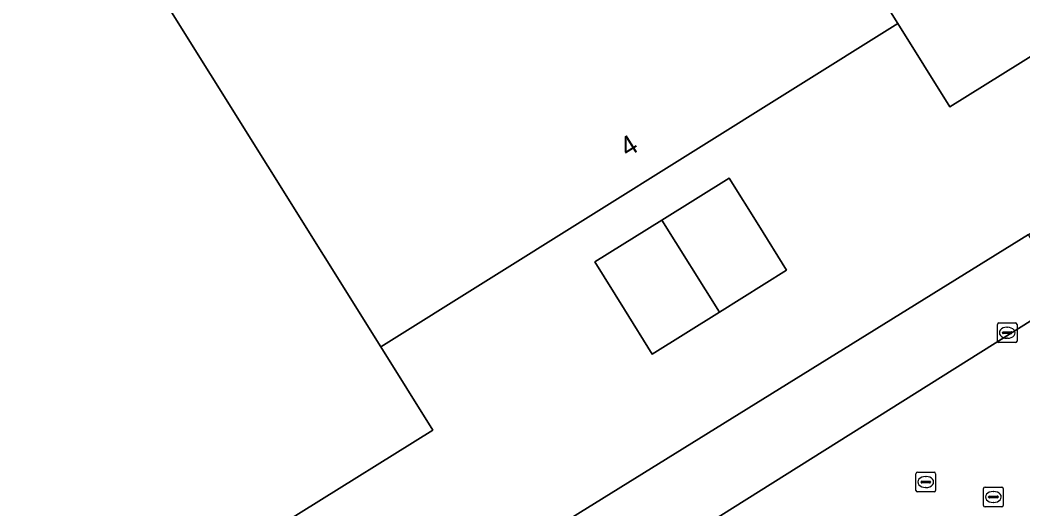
# Model space of a CAD drawing. Extents: x 158455 to 159797, y 387218 to 388672.
# Drawn here: x 158669.4 to 158720.5, y 387869.8 to 387894.7 of the extents above; entities that cross this region are included whole.
import ezdxf

# ---------------------------------------------------------------- set-up
doc = ezdxf.new("R2010")
doc.units = 0
for name, color, linetype in [('IMGEO_Erf', 7, 'Continuous'), ('IMGEO_Kolk', 7, 'Continuous'), ('IMGEO_Pand', 7, 'Continuous'), ('IMGEO_Pand_nummerreeks', 7, 'Continuous'), ('IMGEO_Rijbaan_lokaal_gesloten', 7, 'Continuous'), ('IMGEO_Rioolput', 7, 'Continuous'), ('IMGEO_Voetpad_open', 7, 'Continuous')]:
    doc.layers.add(name, color=color, linetype=linetype)

msp = doc.modelspace()

# ---------------------------------------------------------------- linework, layer by layer
at = {"layer": 'IMGEO_Erf'}
for points in [[(158744.632, 387907.644), (158716.744, 387890.253), (158714.098, 387894.495), (158687.775, 387878.041), (158690.425, 387873.793), (158677.015, 387865.43), (158667.384, 387859.424), (158662.454, 387856.35), (158644.272, 387885.505), (158643.854, 387886.176), (158641.521, 387884.673), (158641.96, 387883.947), (158641.155, 387883.425), (158643.018, 387880.44), (158642.777, 387880.261), (158649.526, 387869.562), (158649.764, 387869.704), (158660.427, 387852.506)], [(158667.843, 387850.68), (158671.035, 387852.64), (158671.42, 387852.913), (158679.517, 387858.122), (158679.905, 387858.319), (158680.956, 387858.977), (158694.549, 387867.497), (158697.049, 387869.064), (158697.447, 387869.303), (158720.745, 387883.755), (158721.126, 387883.994), (158737.622, 387894.417), (158738.014, 387894.663), (158743.631, 387898.186), (158744.037, 387898.407), (158746.473, 387899.899)]]:
    msp.add_lwpolyline(points, dxfattribs=at)
msp.add_lwpolyline([(158707.015, 387884.214), (158708.438, 387881.932), (158705.017, 387879.799), (158701.596, 387877.666), (158700.181, 387879.936), (158698.67, 387882.359), (158702.082, 387884.486), (158705.512, 387886.625)], close=True, dxfattribs=at)
at = {"layer": 'IMGEO_Kolk'}
for p, q in [((158719.167, 387878.324), (158719.167, 387879.176)), ((158719.242, 387879.25), (158720.094, 387879.25)), ((158720.168, 387879.176), (158720.168, 387878.324)), ((158719.426, 387878.744), (158719.426, 387878.756)), ((158719.864, 387878.707), (158719.466, 387878.707)), ((158719.469, 387878.793), (158719.867, 387878.793)), ((158719.655, 387879.03), (158719.68, 387879.03)), ((158719.91, 387878.756), (158719.91, 387878.744)), ((158720.094, 387878.25), (158719.242, 387878.25)), ((158719.678, 387878.47), (158719.653, 387878.47))]:
    msp.add_line(p, q, dxfattribs=at)
for points in [[(158719.167, 387878.324), (158719.167, 387879.176)], [(158719.242, 387879.25), (158720.094, 387879.25)], [(158720.168, 387879.176), (158720.168, 387878.324)], [(158720.094, 387878.25), (158719.242, 387878.25)]]:
    msp.add_lwpolyline(points, dxfattribs=at)
for centre, radius, start, end in [((158719.244, 387879.174), 0.0765, 91.552, 178.448), ((158719.244, 387879.174), 0.0765, 91.552, 178.448), ((158720.092, 387879.174), 0.0765, 1.552, 88.448), ((158720.092, 387879.174), 0.0765, 1.552, 88.448), ((158719.466, 387878.753), 0.0403, 85.8775, 175.7526), ((158719.463, 387878.743), 0.0366, 178.938, 274.7102), ((158719.867, 387878.75), 0.043, 264.8664, 352.4533), ((158719.871, 387878.755), 0.0386, 1.7309, 96.639), ((158719.244, 387878.326), 0.0765, 181.552, 268.448), ((158719.244, 387878.326), 0.0765, 181.552, 268.448), ((158720.092, 387878.326), 0.0765, 271.552, 358.448), ((158720.092, 387878.326), 0.0765, 271.552, 358.448)]:
    msp.add_arc(centre, radius, start, end, dxfattribs=at)
for centre, major_axis, ratio, start_param, end_param in [((158719.654, 387878.75), (-0.387, 0.002), 0.722429, 4.712389, 7.853982), ((158719.679, 387878.75), (-0.39, 0.002), 0.717154, 1.570796, 4.712389)]:
    msp.add_ellipse(centre, major_axis=major_axis, ratio=ratio, start_param=start_param, end_param=end_param, dxfattribs=at)
at = {"layer": 'IMGEO_Pand'}
for points in [[(158676.61, 387954.348), (158714.098, 387894.495), (158716.744, 387890.253), (158744.632, 387907.644), (158718.89, 387948.844), (158715.414, 387954.407), (158714.151, 387956.428), (158704.296, 387972.201), (158703.378, 387971.725), (158698.855, 387972.584), (158698.268, 387973.691), (158673.995, 387958.537)], [(158676.61, 387954.348), (158650.308, 387937.927), (158687.775, 387878.041), (158714.098, 387894.495)], [(158650.308, 387937.927), (158647.66, 387942.169), (158619.858, 387924.778), (158637.955, 387895.772), (158638.476, 387894.936), (158636.079, 387893.406), (158641.521, 387884.673), (158643.854, 387886.176), (158644.272, 387885.505), (158662.454, 387856.35), (158667.384, 387859.424), (158677.015, 387865.43), (158690.425, 387873.793), (158687.775, 387878.041)], [(158702.082, 387884.486), (158705.017, 387879.799), (158708.438, 387881.932), (158707.015, 387884.214), (158705.512, 387886.625)], [(158702.082, 387884.486), (158698.67, 387882.359), (158700.181, 387879.936), (158701.596, 387877.666), (158705.017, 387879.799)]]:
    msp.add_lwpolyline(points, close=True, dxfattribs=at)
at = {"layer": 'IMGEO_Rijbaan_lokaal_gesloten'}
msp.add_lwpolyline([(158748.991, 387897.254), (158748.276, 387896.54), (158747.402, 387895.845), (158737.557, 387889.73), (158736.719, 387889.215), (158726.151, 387882.608), (158724.947, 387881.922), (158697.138, 387864.442), (158696.248, 387863.897), (158685.09, 387856.909), (158684.223, 387856.364), (158671.278, 387848.209)], dxfattribs=at)
at = {"layer": 'IMGEO_Rioolput'}
for p, q in [((158715.021, 387870.72), (158715.021, 387871.572)), ((158715.096, 387871.646), (158715.948, 387871.646)), ((158715.509, 387871.426), (158715.534, 387871.426)), ((158716.022, 387871.572), (158716.022, 387870.72)), ((158715.28, 387871.14), (158715.28, 387871.152)), ((158715.718, 387871.103), (158715.32, 387871.103)), ((158715.323, 387871.189), (158715.721, 387871.189)), ((158715.764, 387871.152), (158715.764, 387871.14)), ((158718.538, 387870.884), (158719.39, 387870.884)), ((158715.948, 387870.646), (158715.096, 387870.646)), ((158715.532, 387870.866), (158715.507, 387870.866)), ((158718.463, 387869.958), (158718.463, 387870.81)), ((158718.722, 387870.378), (158718.722, 387870.39)), ((158718.765, 387870.427), (158719.163, 387870.427)), ((158718.951, 387870.664), (158718.976, 387870.664)), ((158719.206, 387870.39), (158719.206, 387870.378)), ((158719.464, 387870.81), (158719.464, 387869.958)), ((158719.39, 387869.884), (158718.538, 387869.884)), ((158719.16, 387870.341), (158718.762, 387870.341)), ((158718.974, 387870.104), (158718.949, 387870.104))]:
    msp.add_line(p, q, dxfattribs=at)
for points in [[(158715.021, 387870.72), (158715.021, 387871.572)], [(158715.096, 387871.646), (158715.948, 387871.646)], [(158716.022, 387871.572), (158716.022, 387870.72)], [(158718.538, 387870.884), (158719.39, 387870.884)], [(158715.948, 387870.646), (158715.096, 387870.646)], [(158718.463, 387869.958), (158718.463, 387870.81)], [(158719.464, 387870.81), (158719.464, 387869.958)], [(158719.39, 387869.884), (158718.538, 387869.884)]]:
    msp.add_lwpolyline(points, dxfattribs=at)
for centre, radius, start, end in [((158715.098, 387871.57), 0.0765, 91.552, 178.448), ((158715.098, 387871.57), 0.0765, 91.552, 178.448), ((158715.946, 387871.57), 0.0765, 1.552, 88.448), ((158715.946, 387871.57), 0.0765, 1.552, 88.448), ((158715.32, 387871.149), 0.0403, 85.8775, 175.7526), ((158715.317, 387871.139), 0.0366, 178.938, 274.7102), ((158715.721, 387871.146), 0.043, 264.8664, 352.4533), ((158715.725, 387871.151), 0.0386, 1.7309, 96.639), ((158718.54, 387870.808), 0.0765, 91.552, 178.448), ((158718.54, 387870.808), 0.0765, 91.552, 178.448), ((158719.388, 387870.808), 0.0765, 1.552, 88.448), ((158719.388, 387870.808), 0.0765, 1.552, 88.448), ((158715.098, 387870.722), 0.0765, 181.552, 268.448), ((158715.098, 387870.722), 0.0765, 181.552, 268.448), ((158715.946, 387870.722), 0.0765, 271.552, 358.448), ((158715.946, 387870.722), 0.0765, 271.552, 358.448), ((158718.762, 387870.387), 0.0403, 85.8775, 175.7526), ((158718.759, 387870.377), 0.0366, 178.938, 274.7102), ((158719.163, 387870.384), 0.043, 264.8664, 352.4533), ((158719.167, 387870.389), 0.0386, 1.7309, 96.639), ((158718.54, 387869.96), 0.0765, 181.552, 268.448), ((158718.54, 387869.96), 0.0765, 181.552, 268.448), ((158719.388, 387869.96), 0.0765, 271.552, 358.448), ((158719.388, 387869.96), 0.0765, 271.552, 358.448)]:
    msp.add_arc(centre, radius, start, end, dxfattribs=at)
for centre, major_axis, ratio, start_param, end_param in [((158715.508, 387871.146), (-0.387, 0.002), 0.722429, 4.712389, 7.853982), ((158715.533, 387871.146), (-0.39, 0.002), 0.717154, 1.570796, 4.712389), ((158718.95, 387870.384), (-0.387, 0.002), 0.722429, 4.712389, 7.853982), ((158718.975, 387870.384), (-0.39, 0.002), 0.717154, 1.570796, 4.712389)]:
    msp.add_ellipse(centre, major_axis=major_axis, ratio=ratio, start_param=start_param, end_param=end_param, dxfattribs=at)
at = {"layer": 'IMGEO_Voetpad_open'}
for points in [[(158721.157, 387883.073), (158720.745, 387883.755), (158697.447, 387869.303), (158697.93, 387868.543)], [(158697.138, 387864.442), (158724.947, 387881.922)]]:
    msp.add_lwpolyline(points, dxfattribs=at)

# ---------------------------------------------------------------- texts
at = {"layer": 'IMGEO_Pand_nummerreeks'}
msp.add_text('4', height=1, rotation=32.0112, dxfattribs=at).set_placement((158700.339, 387887.663))

doc.saveas('drawing.dxf')
